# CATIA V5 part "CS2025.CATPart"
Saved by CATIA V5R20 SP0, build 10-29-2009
Part number: CS2025
Revision: 5
Definition: design
Nomenclature: CS2025
Source: made
Description: NOT SPECIFIED
Bounding box of the stored display mesh (mm): x -23.825 to 24, y -24 to 24, z -45 to 12
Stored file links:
  C:\Users\Raffaele\Desktop\3D X SITO CF\BOLEX\20-TILTED COLUMN SUPPORT\CS2025.CATPart
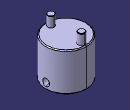
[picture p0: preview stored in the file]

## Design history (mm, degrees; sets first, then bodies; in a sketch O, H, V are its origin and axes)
Body1 "MANIFOLD_SOLID_BREP #711" (main body)
  Solid1: solid without history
